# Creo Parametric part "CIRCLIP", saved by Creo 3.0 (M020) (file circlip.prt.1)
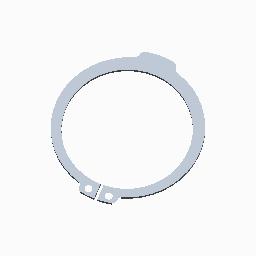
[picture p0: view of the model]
Units: millimeter Kilogram Sec (mmKs); MM, KILOGRAM, SECS

Created from: SOLID_PART_MMKS.PRT

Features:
  1. coordinate system
  2. datum plane "RIGHT"
  3. datum plane "TOP"
  4. datum plane "FRONT"
  5. sketch "Sketch 1", "A_1"
  6. extrusion "Extrude 1"
  7. round "Round 1"
  8. round "Round 2"
  9. round "Round 3"

Surfaces: 19 cylinder, 9 plane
